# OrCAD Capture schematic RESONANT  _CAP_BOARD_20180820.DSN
size A3
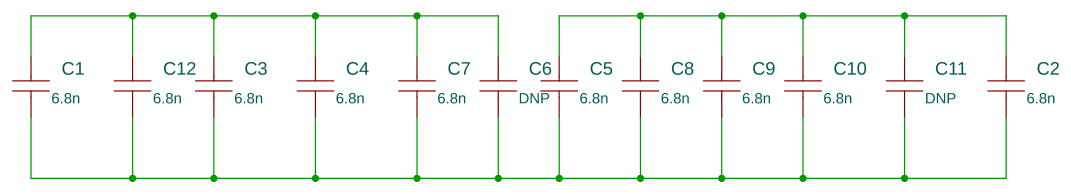
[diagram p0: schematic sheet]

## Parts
C1  6.8n  [B32651A7682J000]
C2  6.8n  [B32651A7682J000]
C3  6.8n  [B32651A7682J000]
C4  6.8n  [B32651A7682J000]
C5  6.8n  [B32651A7682J000]
C6  DNP  [B32651A7682J000]
C7  6.8n  [B32651A7682J000]
C8  6.8n  [B32651A7682J000]
C9  6.8n  [B32651A7682J000]
C10  6.8n  [B32651A7682J000]
C11  DNP  [B32651A7682J000]
C12  6.8n  [B32651A7682J000]

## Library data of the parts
C1-C12 = CAP_NP

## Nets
N00405: C1.1 C3.1 C4.1 C6.1 C7.1 C12.1
N00421: C1.2 C2.2 C3.2 C4.2 C5.2 C6.2 C7.2 C8.2 C9.2 C10.2 C11.2 C12.2
N00657: C2.1 C5.1 C8.1 C9.1 C10.1 C11.1
